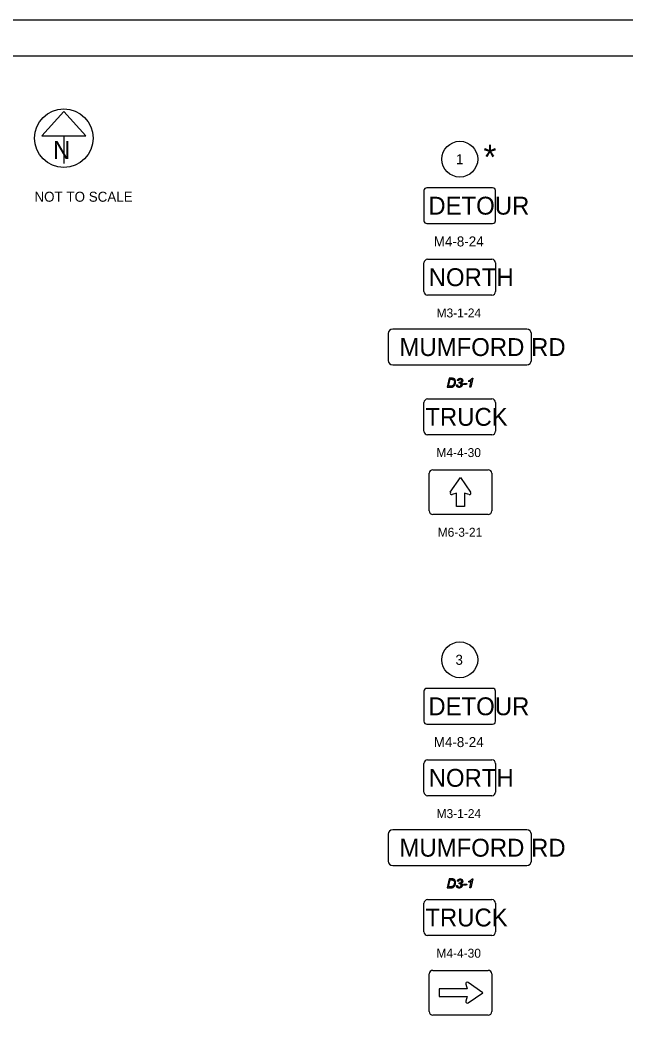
# Model space of a CAD drawing. Extents: x -0.3 to 34, y 0 to 22.
# Drawn here: x 16.2 to 24.67, y 7.96 to 22 of the extents above; entities that cross this region are included whole.
import ezdxf

# ---------------------------------------------------------------- set-up
doc = ezdxf.new("R2010")
doc.units = 0
for name, color, linetype in [('GM_X_Adjacent_County_Text', 7, 'Continuous'), ('GM_X_County', 7, 'Continuous'), ('GM_X_Minor_Lake_Text', 7, 'Continuous'), ('GM_X_Minor_River_Text', 7, 'Continuous'), ('GM_X_Section', 7, 'Continuous'), ('GM_X_Township_Road', 7, 'Continuous')]:
    doc.layers.add(name, color=color, linetype=linetype)

msp = doc.modelspace()

# ---------------------------------------------------------------- linework, layer by layer
at = {"layer": 'GM_X_Adjacent_County_Text'}
for p, q in [((16.811, 20.724), (16.504, 20.383)), ((17.119, 20.383), (16.811, 20.724)), ((16.504, 20.383), (17.119, 20.383)), ((16.811, 20.383), (16.811, 19.996))]:
    msp.add_line(p, q, dxfattribs=at)
msp.add_circle((16.811, 20.35), 0.41, dxfattribs=at)
at = {"layer": 'GM_X_County'}
msp.add_lwpolyline([(1.5, 21.5), (33.5, 21.5), (33.5, 0.5), (1.5, 0.5)], close=True, dxfattribs=at)
at = {"layer": 'GM_X_Minor_Lake_Text'}
for p, q in [((22.298, 16.899), (22.313, 16.901)), ((22.327, 16.956), (22.312, 16.959)), ((22.336, 16.924), (22.339, 16.937)), ((22.47, 16.944), (22.473, 16.958)), ((22.298, 9.899), (22.313, 9.901)), ((22.327, 9.956), (22.312, 9.959)), ((22.336, 9.924), (22.339, 9.937)), ((22.47, 9.944), (22.473, 9.958))]:
    msp.add_line(p, q, dxfattribs=at)
for points in [[(22.234, 16.991), (22.197, 16.991), (22.17, 16.866), (22.216, 16.866)], [(22.519, 16.991), (22.528, 16.991), (22.502, 16.866), (22.486, 16.866), (22.506, 16.96)], [(22.21, 16.88), (22.19, 16.88), (22.21, 16.977), (22.232, 16.977)], [(22.234, 9.991), (22.197, 9.991), (22.17, 9.866), (22.216, 9.866)], [(22.21, 9.88), (22.19, 9.88), (22.21, 9.977), (22.232, 9.977)], [(22.519, 9.991), (22.528, 9.991), (22.502, 9.866), (22.486, 9.866), (22.506, 9.96)]]:
    msp.add_lwpolyline(points, dxfattribs=at)
for points in [[(22.394, 16.903), (22.397, 16.919), (22.444, 16.919), (22.441, 16.903)], [(22.394, 9.903), (22.397, 9.919), (22.444, 9.919), (22.441, 9.903)]]:
    msp.add_lwpolyline(points, close=True, dxfattribs=at)
for centre in [(22.346, 20.055), (22.346, 13.055)]:
    msp.add_circle(centre, 0.25, dxfattribs=at)
for points in [[(22.255, 16.989), (22.248, 16.991), (22.234, 16.991)], [(22.272, 16.98), (22.265, 16.986), (22.255, 16.989)], [(22.327, 16.983), (22.337, 16.991), (22.352, 16.991)], [(22.352, 16.991), (22.367, 16.991), (22.377, 16.982)], [(22.512, 16.983), (22.516, 16.987), (22.519, 16.991)], [(22.234, 16.883), (22.223, 16.88), (22.21, 16.88)], [(22.216, 16.866), (22.228, 16.866), (22.236, 16.868)], [(22.232, 16.977), (22.245, 16.977), (22.251, 16.975)], [(22.245, 16.887), (22.24, 16.884), (22.234, 16.883)], [(22.236, 16.868), (22.247, 16.87), (22.255, 16.876)], [(22.256, 16.897), (22.251, 16.891), (22.245, 16.887)], [(22.251, 16.975), (22.26, 16.972), (22.265, 16.964)], [(22.255, 16.876), (22.263, 16.881), (22.271, 16.891)], [(22.266, 16.916), (22.262, 16.906), (22.256, 16.897)], [(22.265, 16.964), (22.27, 16.956), (22.27, 16.941)], [(22.27, 16.941), (22.27, 16.927), (22.266, 16.916)], [(22.271, 16.891), (22.278, 16.9), (22.283, 16.912)], [(22.283, 16.963), (22.28, 16.973), (22.272, 16.98)], [(22.287, 16.94), (22.287, 16.952), (22.283, 16.963)], [(22.283, 16.912), (22.287, 16.925), (22.287, 16.94)], [(22.31, 16.873), (22.3, 16.883), (22.298, 16.899)], [(22.337, 16.864), (22.32, 16.864), (22.31, 16.873)], [(22.312, 16.959), (22.316, 16.974), (22.327, 16.983)], [(22.313, 16.901), (22.315, 16.887), (22.321, 16.882)], [(22.321, 16.882), (22.327, 16.876), (22.336, 16.876)], [(22.336, 16.973), (22.329, 16.967), (22.327, 16.956)], [(22.351, 16.979), (22.342, 16.979), (22.336, 16.973)], [(22.341, 16.924), (22.34, 16.924), (22.336, 16.924)], [(22.336, 16.876), (22.348, 16.876), (22.356, 16.884)], [(22.368, 16.876), (22.355, 16.864), (22.337, 16.864)], [(22.339, 16.937), (22.341, 16.936), (22.343, 16.936)], [(22.358, 16.918), (22.352, 16.924), (22.341, 16.924)], [(22.343, 16.936), (22.356, 16.936), (22.364, 16.943)], [(22.365, 16.973), (22.359, 16.979), (22.351, 16.979)], [(22.356, 16.884), (22.364, 16.892), (22.364, 16.903)], [(22.364, 16.903), (22.364, 16.912), (22.358, 16.918)], [(22.364, 16.943), (22.371, 16.949), (22.371, 16.959)], [(22.371, 16.959), (22.371, 16.967), (22.365, 16.973)], [(22.381, 16.942), (22.376, 16.935), (22.365, 16.93)], [(22.365, 16.93), (22.373, 16.925), (22.376, 16.919)], [(22.38, 16.905), (22.38, 16.888), (22.368, 16.876)], [(22.376, 16.919), (22.38, 16.913), (22.38, 16.905)], [(22.377, 16.982), (22.386, 16.973), (22.386, 16.959)], [(22.386, 16.959), (22.386, 16.949), (22.381, 16.942)], [(22.506, 16.96), (22.493, 16.95), (22.47, 16.944)], [(22.473, 16.958), (22.484, 16.963), (22.495, 16.97)], [(22.495, 16.97), (22.507, 16.978), (22.512, 16.983)], [(22.232, 9.977), (22.245, 9.977), (22.251, 9.975)], [(22.255, 9.989), (22.248, 9.991), (22.234, 9.991)], [(22.251, 9.975), (22.26, 9.972), (22.265, 9.964)], [(22.272, 9.98), (22.265, 9.986), (22.255, 9.989)], [(22.283, 9.963), (22.28, 9.973), (22.272, 9.98)], [(22.312, 9.959), (22.316, 9.974), (22.327, 9.983)], [(22.327, 9.983), (22.337, 9.991), (22.352, 9.991)], [(22.336, 9.973), (22.329, 9.967), (22.327, 9.956)], [(22.351, 9.979), (22.342, 9.979), (22.336, 9.973)], [(22.365, 9.973), (22.359, 9.979), (22.351, 9.979)], [(22.352, 9.991), (22.367, 9.991), (22.377, 9.982)], [(22.371, 9.959), (22.371, 9.967), (22.365, 9.973)], [(22.377, 9.982), (22.386, 9.973), (22.386, 9.959)], [(22.473, 9.958), (22.484, 9.963), (22.495, 9.97)], [(22.495, 9.97), (22.507, 9.978), (22.512, 9.983)], [(22.512, 9.983), (22.516, 9.987), (22.519, 9.991)], [(22.234, 9.883), (22.223, 9.88), (22.21, 9.88)], [(22.216, 9.866), (22.228, 9.866), (22.236, 9.868)], [(22.245, 9.887), (22.24, 9.884), (22.234, 9.883)], [(22.236, 9.868), (22.247, 9.87), (22.255, 9.876)], [(22.256, 9.897), (22.251, 9.891), (22.245, 9.887)], [(22.255, 9.876), (22.263, 9.881), (22.271, 9.891)], [(22.266, 9.916), (22.262, 9.906), (22.256, 9.897)], [(22.265, 9.964), (22.27, 9.956), (22.27, 9.941)], [(22.27, 9.941), (22.27, 9.927), (22.266, 9.916)], [(22.271, 9.891), (22.278, 9.9), (22.283, 9.912)], [(22.287, 9.94), (22.287, 9.952), (22.283, 9.963)], [(22.283, 9.912), (22.287, 9.925), (22.287, 9.94)], [(22.31, 9.873), (22.3, 9.883), (22.298, 9.899)], [(22.337, 9.864), (22.32, 9.864), (22.31, 9.873)], [(22.313, 9.901), (22.315, 9.887), (22.321, 9.882)], [(22.321, 9.882), (22.327, 9.876), (22.336, 9.876)], [(22.341, 9.924), (22.34, 9.924), (22.336, 9.924)], [(22.336, 9.876), (22.348, 9.876), (22.356, 9.884)], [(22.368, 9.876), (22.355, 9.864), (22.337, 9.864)], [(22.339, 9.937), (22.341, 9.936), (22.343, 9.936)], [(22.358, 9.918), (22.352, 9.924), (22.341, 9.924)], [(22.343, 9.936), (22.356, 9.936), (22.364, 9.943)], [(22.356, 9.884), (22.364, 9.892), (22.364, 9.903)], [(22.364, 9.903), (22.364, 9.912), (22.358, 9.918)], [(22.364, 9.943), (22.371, 9.949), (22.371, 9.959)], [(22.381, 9.942), (22.376, 9.935), (22.365, 9.93)], [(22.365, 9.93), (22.373, 9.925), (22.376, 9.919)], [(22.38, 9.905), (22.38, 9.888), (22.368, 9.876)], [(22.376, 9.919), (22.38, 9.913), (22.38, 9.905)], [(22.386, 9.959), (22.386, 9.949), (22.381, 9.942)], [(22.506, 9.96), (22.493, 9.95), (22.47, 9.944)]]:
    msp.add_open_spline(points, degree=2, dxfattribs=at)
at = {"layer": 'GM_X_Minor_River_Text'}
for p, q in [((21.845, 18.205), (21.845, 18.605)), ((21.895, 18.655), (22.795, 18.655)), ((22.845, 18.605), (22.845, 18.205)), ((22.795, 18.155), (21.895, 18.155)), ((21.845, 16.252), (21.845, 16.652)), ((21.895, 16.702), (22.795, 16.702)), ((22.845, 16.652), (22.845, 16.252)), ((22.795, 16.202), (21.895, 16.202)), ((21.918, 15.138), (21.918, 15.663)), ((21.968, 15.713), (22.743, 15.713)), ((22.213, 15.397), (22.356, 15.604)), ((22.356, 15.604), (22.495, 15.4)), ((22.793, 15.663), (22.793, 15.138)), ((22.301, 15.385), (22.237, 15.365)), ((22.301, 15.198), (22.301, 15.385)), ((22.474, 15.365), (22.41, 15.385)), ((22.41, 15.385), (22.41, 15.198)), ((22.41, 15.198), (22.301, 15.198)), ((22.743, 15.088), (21.968, 15.088)), ((21.895, 11.655), (22.795, 11.655)), ((21.845, 11.205), (21.845, 11.605)), ((22.845, 11.605), (22.845, 11.205)), ((22.795, 11.155), (21.895, 11.155)), ((21.895, 9.702), (22.795, 9.702)), ((21.845, 9.252), (21.845, 9.652)), ((22.845, 9.652), (22.845, 9.252)), ((22.795, 9.202), (21.895, 9.202)), ((21.968, 8.713), (22.743, 8.713)), ((21.918, 8.138), (21.918, 8.663)), ((22.793, 8.663), (22.793, 8.138)), ((22.449, 8.455), (22.059, 8.455)), ((22.059, 8.455), (22.059, 8.346)), ((22.429, 8.52), (22.449, 8.455)), ((22.668, 8.401), (22.461, 8.543)), ((22.059, 8.346), (22.449, 8.346)), ((22.449, 8.346), (22.429, 8.282)), ((22.464, 8.261), (22.668, 8.401)), ((22.743, 8.088), (21.968, 8.088))]:
    msp.add_line(p, q, dxfattribs=at)
for points in [[(22.805, 19.655), (21.885, 19.655)], [(21.845, 19.615), (21.845, 19.195)], [(22.845, 19.195), (22.845, 19.615)], [(21.885, 19.155), (22.805, 19.155)], [(21.345, 17.616), (21.345, 17.241)], [(23.283, 17.678), (21.408, 17.678)], [(23.345, 17.616), (23.345, 17.241)], [(21.408, 17.178), (23.283, 17.178)], [(22.805, 12.655), (21.885, 12.655)], [(21.845, 12.615), (21.845, 12.195)], [(22.845, 12.195), (22.845, 12.615)], [(21.885, 12.155), (22.805, 12.155)], [(23.283, 10.678), (21.408, 10.678)], [(21.345, 10.616), (21.345, 10.241)], [(23.345, 10.616), (23.345, 10.241)], [(21.408, 10.178), (23.283, 10.178)]]:
    msp.add_lwpolyline(points, dxfattribs=at)
for centre, radius, start, end in [((21.885, 19.615), 0.04, 90, 180), ((22.805, 19.615), 0.04, 0, 90), ((21.885, 19.195), 0.04, 180, 270), ((22.805, 19.195), 0.04, 270, 0), ((21.895, 18.605), 0.05, 90, 180), ((22.795, 18.605), 0.05, 0, 90), ((21.895, 18.205), 0.05, 180, 270), ((22.795, 18.205), 0.05, 270, 0), ((21.408, 17.616), 0.0625, 90, 180), ((23.283, 17.616), 0.0625, 0, 90), ((21.408, 17.241), 0.0625, 180, 270), ((23.283, 17.241), 0.0625, 270, 0), ((21.895, 16.652), 0.05, 90, 180), ((22.795, 16.652), 0.05, 0, 90), ((21.895, 16.252), 0.05, 180, 270), ((22.795, 16.252), 0.05, 270, 360), ((21.968, 15.663), 0.05, 90, 180), ((22.743, 15.663), 0.05, 0, 90), ((22.231, 15.385), 0.0209, 145.4112, 287.2046), ((22.481, 15.385), 0.0209, 252.7954, 45.0096), ((21.968, 15.138), 0.05, 180, 270), ((22.743, 15.138), 0.05, 270, 0), ((21.885, 12.615), 0.04, 90, 180), ((22.805, 12.615), 0.04, 0, 90), ((21.885, 12.195), 0.04, 180, 270), ((22.805, 12.195), 0.04, 270, 0), ((21.895, 11.605), 0.05, 90, 180), ((22.795, 11.605), 0.05, 0, 90), ((21.895, 11.205), 0.05, 180, 270), ((22.795, 11.205), 0.05, 270, 0), ((21.408, 10.616), 0.0625, 90, 180), ((23.283, 10.616), 0.0625, 0, 90), ((21.408, 10.241), 0.0625, 180, 270), ((23.283, 10.241), 0.0625, 270, 0), ((21.895, 9.652), 0.05, 90, 180), ((22.795, 9.652), 0.05, 0, 90), ((21.895, 9.252), 0.05, 180, 270), ((22.795, 9.252), 0.05, 270, 360), ((21.968, 8.663), 0.05, 90, 180), ((22.743, 8.663), 0.05, 0, 90), ((22.449, 8.526), 0.0209, 55.4112, 197.2046), ((22.449, 8.276), 0.0209, 162.7954, 315.0096), ((21.968, 8.138), 0.05, 180, 270), ((22.743, 8.138), 0.05, 270, 360)]:
    msp.add_arc(centre, radius, start, end, dxfattribs=at)
at = {"layer": 'GM_X_Section'}
msp.add_lwpolyline([(0, 0), (34, 0), (34, 22), (0, 22)], close=True, dxfattribs=at)
at = {"layer": 'GM_X_Township_Road'}
msp.add_circle((16.811, 20.35), 0.41, dxfattribs=at)

# ---------------------------------------------------------------- texts
at = {"layer": 'GM_X_Adjacent_County_Text'}
for s, height, p in [('N', 0.25, (16.66, 20.059)), ('*', 0.35, (22.676, 19.91)), ('NOT TO SCALE', 0.14, (16.401, 19.46))]:
    msp.add_text(s, height=height, dxfattribs=at).set_placement(p)
at = {"layer": 'GM_X_Minor_Lake_Text'}
for s, height, p in [('1', 0.14, (22.292, 19.985)), ('M4-8-24', 0.14, (21.982, 18.835)), ('M3-1-24', 0.125, (22.021, 17.842)), ('M4-4-30', 0.125, (22.019, 15.89)), ('M6-3-21', 0.125, (22.037, 14.776)), ('3', 0.14, (22.285, 12.985)), ('M4-8-24', 0.14, (21.982, 11.835)), ('M3-1-24', 0.125, (22.021, 10.842)), ('M4-4-30', 0.125, (22.019, 8.89))]:
    msp.add_text(s, height=height, dxfattribs=at).set_placement(p)
at = {"layer": 'GM_X_Minor_River_Text'}
for s, p in [('DETOUR', (21.906, 19.28)), ('NORTH', (21.911, 18.28)), ('MUMFORD RD', (21.503, 17.303)), ('TRUCK', (21.864, 16.327)), ('DETOUR', (21.906, 12.28)), ('NORTH', (21.911, 11.28)), ('MUMFORD RD', (21.503, 10.303)), ('TRUCK', (21.864, 9.327))]:
    msp.add_text(s, height=0.25, dxfattribs=at).set_placement(p)

doc.saveas('drawing.dxf')
